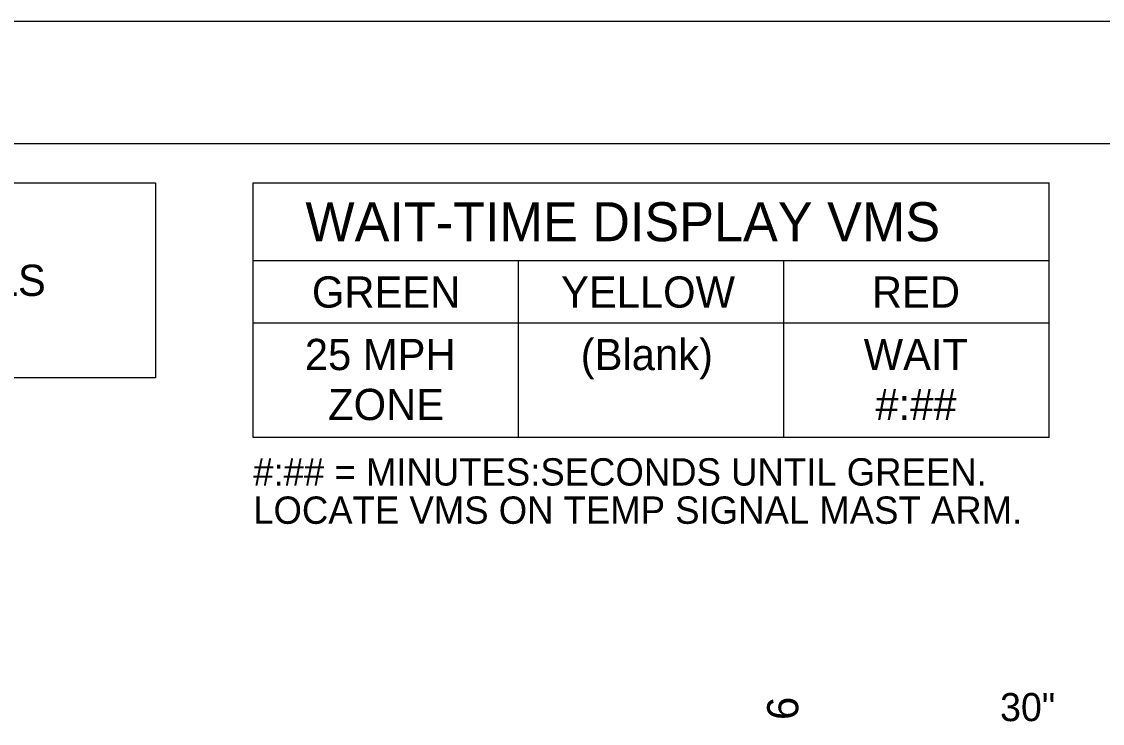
# Model space of a CAD drawing. Extents: x 99979.8 to 100075.7, y 99995 to 100010.7.
# Drawn here: x 100022.228 to 100024.999, y 100008.89 to 100010.687 of the extents above; entities that cross this region are included whole.
import ezdxf

# ---------------------------------------------------------------- set-up
doc = ezdxf.new("R2010")
doc.units = 0
for name, color, linetype in [('SH_GI_PlotLimits', 7, 'Continuous'), ('SH_GI_SheetBorder', 7, 'Continuous'), ('SH_TI_Tables', 7, 'Continuous'), ('TR_SN_ConstructionSigns', 7, 'Continuous'), ('TR_WZ_PortableChangeMessageSign', 7, 'Continuous'), ('TR_WZ_WorkZoneTextCurrent', 7, 'Continuous')]:
    doc.layers.add(name, color=color, linetype=linetype)

msp = doc.modelspace()

# ---------------------------------------------------------------- linework, layer by layer
at = {"layer": 'SH_GI_PlotLimits'}
msp.add_lwpolyline([(100019.0625, 99999.6875), (100036.0625, 99999.6875), (100036.0625, 100010.6875), (100019.0625, 100010.6875)], close=True, dxfattribs=at)
at = {"layer": 'SH_GI_SheetBorder'}
msp.add_line((100020, 100010.375), (100035.75, 100010.375), dxfattribs=at)
at = {"layer": 'SH_TI_Tables'}
msp.add_lwpolyline([(100020.1, 100010.275), (100022.5718, 100010.275), (100022.5718, 100009.775), (100020.1, 100009.775)], close=True, dxfattribs=at)
at = {"layer": 'TR_WZ_PortableChangeMessageSign'}
for p, q in [((100022.8218, 100010.275), (100024.8618, 100010.275)), ((100022.8218, 100009.6227), (100022.8218, 100010.275)), ((100024.8618, 100009.6227), (100024.8618, 100010.275)), ((100024.8618, 100010.075), (100022.8218, 100010.075)), ((100023.5018, 100009.6227), (100023.5018, 100010.075)), ((100024.1818, 100009.6227), (100024.1818, 100010.075)), ((100023.5018, 100009.915), (100022.8218, 100009.915)), ((100024.1818, 100009.915), (100023.5018, 100009.915)), ((100024.8618, 100009.915), (100024.1818, 100009.915)), ((100024.8618, 100009.6227), (100022.8218, 100009.6227))]:
    msp.add_line(p, q, dxfattribs=at)

# ---------------------------------------------------------------- texts
at = {"layer": 'SH_TI_Tables'}
msp.add_text('AND INTERSECTING ROADWAY DETAILS', height=0.08, rotation=360, dxfattribs=at).set_placement((100020.18, 100009.985))
at = {"layer": 'TR_SN_ConstructionSigns'}
msp.add_text('30"', height=0.072, rotation=360, dxfattribs=at).set_placement((100024.7363, 100008.8959))
at = {"layer": 'TR_WZ_PortableChangeMessageSign'}
for s, height, p in [('WAIT-TIME DISPLAY VMS', 0.1, (100022.9556, 100010.125)), ('GREEN', 0.08, (100022.9724, 100009.955)), ('YELLOW', 0.08, (100023.6109, 100009.955)), ('RED', 0.08, (100024.4078, 100009.955)), ('(Blank)', 0.08, (100023.6614, 100009.795)), ('25 MPH', 0.08, (100022.9542, 100009.795)), ('WAIT', 0.08, (100024.3868, 100009.795)), ('ZONE', 0.08, (100023.0139, 100009.667)), ('#:##', 0.08, (100024.4169, 100009.667)), ('#:## = MINUTES:SECONDS UNTIL GREEN.', 0.07, (100022.8218, 100009.4993)), ('LOCATE VMS ON TEMP SIGNAL MAST ARM.', 0.07, (100022.8218, 100009.4013))]:
    msp.add_text(s, height=height, rotation=360, dxfattribs=at).set_placement(p)
at = {"layer": 'TR_WZ_WorkZoneTextCurrent'}
msp.add_text('6', height=0.08, rotation=90, dxfattribs=at).set_placement((100024.2191, 100008.8988))

doc.saveas('drawing.dxf')
